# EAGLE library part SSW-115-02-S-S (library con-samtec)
THROUGH-HOLE .025" SQ POST SOCKET Source: Samtec SSW.pdf
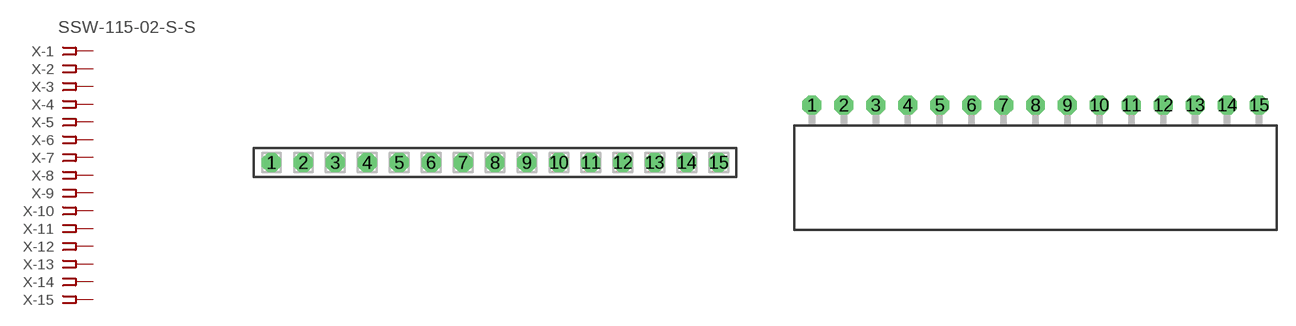
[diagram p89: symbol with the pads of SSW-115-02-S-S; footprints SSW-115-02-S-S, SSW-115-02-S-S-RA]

Designator prefix X; gates -1=FPINV -2=FPIN -3=FPIN -4=FPIN -5=FPIN -6=FPIN -7=FPIN -8=FPIN -9=FPIN -10=FPIN -11=FPIN -12=FPIN -13=FPIN -14=FPIN -15=FPIN

## SSW-115-02-S-S (MPN: SSW-115-02-S-S; OC_FARNELL: unknown; OC_NEWARK: 11P9564)  [SSW-115-02-S-S]
1  -1:1  pas
2  -2:1  pas
3  -3:1  pas
4  -4:1  pas
5  -5:1  pas
6  -6:1  pas
7  -7:1  pas
8  -8:1  pas
9  -9:1  pas
10  -10:1  pas
11  -11:1  pas
12  -12:1  pas
13  -13:1  pas
14  -14:1  pas
15  -15:1  pas

## SSW-115-02-S-S-RA (MPN: SSW-115-02-S-S-RA; OC_FARNELL: unknown; OC_NEWARK: 11P9565)  [SSW-115-02-S-S-RA]
Pads as for SSW-115-02-S-S

## Footprint SSW-115-02-S-S (pad centres in mm)
THROUGH-HOLE .025" SQ POST SOCKET Source: Samtec SSW.pdf
drill 1 pad 1.5 octagon: 1 -17.78,0; 2 -15.24,0; 3 -12.7,0; 4 -10.16,0; 5 -7.62,0; 6 -5.08,0; 7 -2.54,0; 8 0,0; 9 2.54,0; 10 5.08,0; 11 7.62,0; 12 10.16,0; 13 12.7,0; 14 15.24,0; 15 17.78,0

## Footprint SSW-115-02-S-S-RA (pad centres in mm)
THROUGH-HOLE .025" SQ POST SOCKET Source: Samtec SSW.pdf
drill 1 pad 1.5 octagon: 1 -17.78,1.524; 2 -15.24,1.524; 3 -12.7,1.524; 4 -10.16,1.524; 5 -7.62,1.524; 6 -5.08,1.524; 7 -2.54,1.524; 8 0,1.524; 9 2.54,1.524; 10 5.08,1.524; 11 7.62,1.524; 12 10.16,1.524; 13 12.7,1.524; 14 15.24,1.524; 15 17.78,1.524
